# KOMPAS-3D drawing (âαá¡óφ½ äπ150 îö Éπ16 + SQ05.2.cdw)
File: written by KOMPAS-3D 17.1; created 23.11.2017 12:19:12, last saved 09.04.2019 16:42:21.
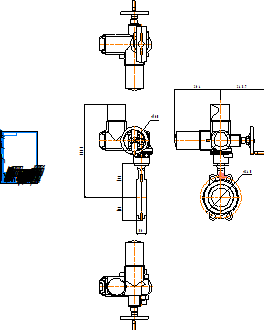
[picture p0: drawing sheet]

Sheet 1: A4, portrait

Title block, sheet 1: name: Гранвэл Ду150 МФ Ру16 + / SQ05.2; material: Внимание! Данный продукт является объектом авторского права ООО «Торговый Дом АДЛ». / Запрещается изменение, копирование, распространение / (в том числе путем копирования на другие сайты и ресурсы в Интернете) / или любое иное использование информации и объектов без предварительного / согласия правообладателя (ООО «Торговый Дом АДЛ»).; mass: 94; sheets: 1; organisation: ООО "Торговый дом АДЛ"; sheet format: A4; stored path: \\adlc.lan\data\АДЛ_ПКД\3D-модели\ADL production\Дисковые поворотные затворы ГРАНВЭЛ\межфланцевый с эл.приводом Auma Ру 16\KOMPAS 2D\Гранвэл Ду150 МФ Ру16 + SQ05.2.cdw

Views: Вид 1, Проекционный вид 4, Проекционный вид 5
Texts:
  kka
  adl
Dimensions and other numbers on the sheet: 536,5; 160; 56; 193; 133; 1:1; 1; 94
